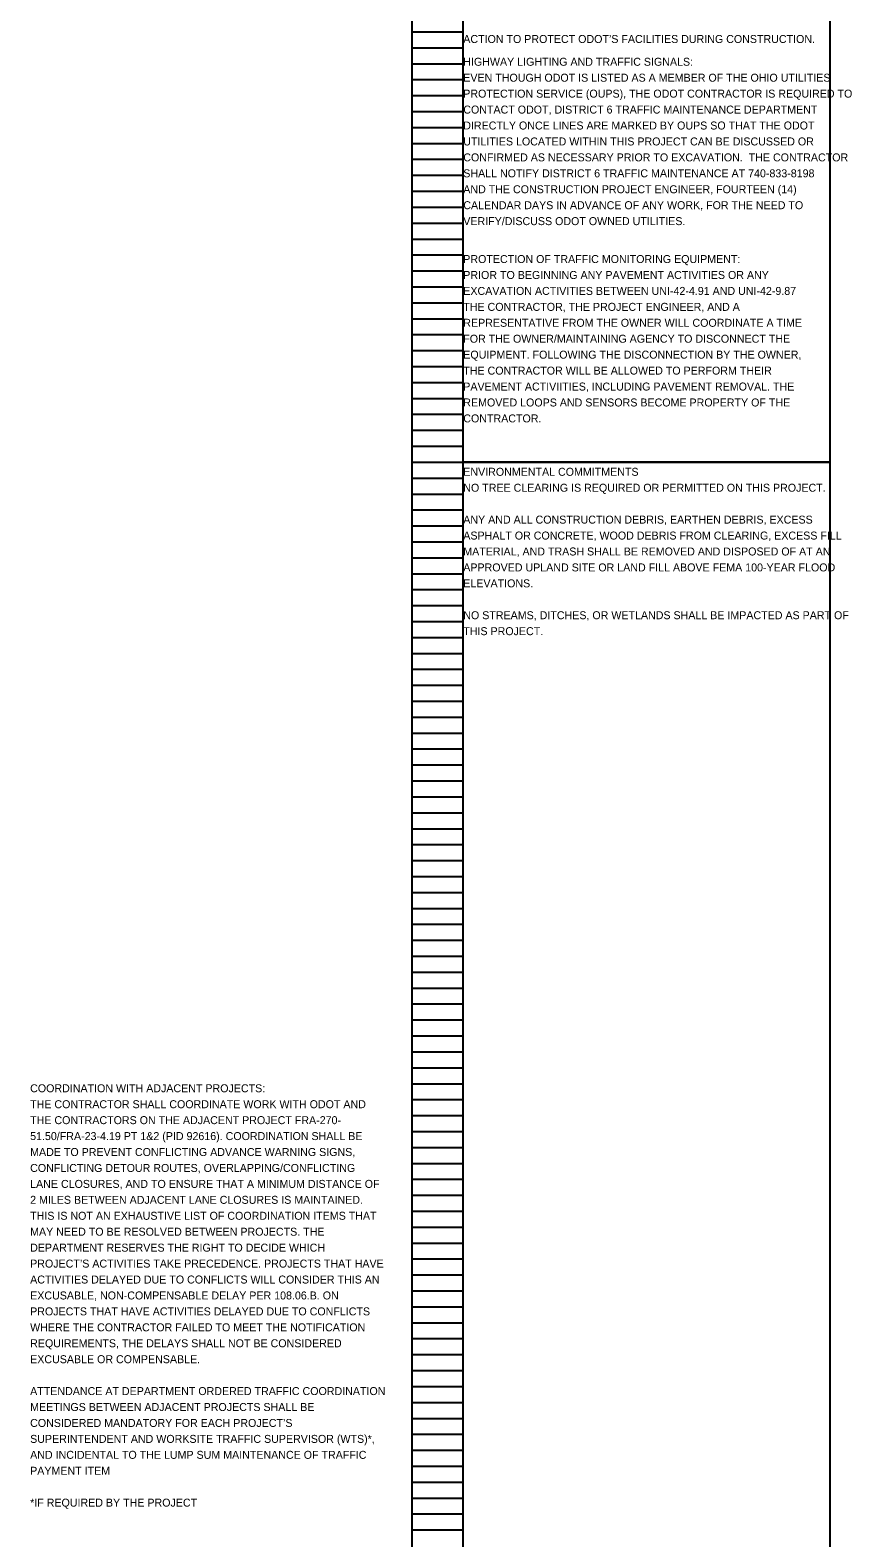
# Model space of a CAD drawing. Extents: x 16456 to 16500, y 5400 to 5823.
# Drawn here: x 16456.34 to 16470.77, y 5744.09 to 5770.58 of the extents above; entities that cross this region are included whole.
import ezdxf

# ---------------------------------------------------------------- set-up
doc = ezdxf.new("R2010")
doc.units = 0
for name, color, linetype in [('Default', 7, 'Continuous'), ('SC_Scratch1', 7, 'Continuous'), ('SH_Data', 7, 'Continuous')]:
    doc.layers.add(name, color=color, linetype=linetype)

msp = doc.modelspace()

# ---------------------------------------------------------------- linework, layer by layer
at = {"layer": 'SC_Scratch1'}
for points in [[(16463.949, 5783.152), (16470.389, 5783.152), (16470.389, 5762.992), (16463.949, 5762.992)], [(16463.949, 5762.992), (16470.389, 5762.992), (16470.389, 5742.832), (16463.949, 5742.832)]]:
    msp.add_lwpolyline(points, close=True, dxfattribs=at)
at = {"layer": 'SH_Data'}
for p, q in [((16463.049, 5762.992), (16463.049, 5783.152)), ((16463.949, 5762.992), (16463.949, 5783.152)), ((16463.049, 5770.552), (16463.949, 5770.552)), ((16463.049, 5770.272), (16463.949, 5770.272)), ((16463.049, 5769.992), (16463.949, 5769.992)), ((16463.049, 5769.712), (16463.949, 5769.712)), ((16463.049, 5769.432), (16463.949, 5769.432)), ((16463.049, 5769.152), (16463.949, 5769.152)), ((16463.049, 5768.872), (16463.949, 5768.872)), ((16463.049, 5768.592), (16463.949, 5768.592)), ((16463.049, 5768.312), (16463.949, 5768.312)), ((16463.049, 5768.032), (16463.949, 5768.032)), ((16463.049, 5767.752), (16463.949, 5767.752)), ((16463.049, 5767.472), (16463.949, 5767.472)), ((16463.049, 5767.192), (16463.949, 5767.192)), ((16463.049, 5766.912), (16463.949, 5766.912)), ((16463.049, 5766.632), (16463.949, 5766.632)), ((16463.049, 5766.352), (16463.949, 5766.352)), ((16463.049, 5766.072), (16463.949, 5766.072)), ((16463.049, 5765.792), (16463.949, 5765.792)), ((16463.049, 5765.512), (16463.949, 5765.512)), ((16463.049, 5765.232), (16463.949, 5765.232)), ((16463.049, 5764.952), (16463.949, 5764.952)), ((16463.049, 5764.672), (16463.949, 5764.672)), ((16463.049, 5764.392), (16463.949, 5764.392)), ((16463.049, 5764.112), (16463.949, 5764.112)), ((16463.049, 5763.832), (16463.949, 5763.832)), ((16463.049, 5763.552), (16463.949, 5763.552)), ((16463.049, 5763.272), (16463.949, 5763.272)), ((16463.049, 5742.832), (16463.049, 5762.992)), ((16463.049, 5762.992), (16463.949, 5762.992)), ((16463.049, 5762.992), (16463.949, 5762.992)), ((16463.949, 5742.832), (16463.949, 5762.992)), ((16463.049, 5762.712), (16463.949, 5762.712)), ((16463.049, 5762.432), (16463.949, 5762.432)), ((16463.049, 5762.152), (16463.949, 5762.152)), ((16463.049, 5761.872), (16463.949, 5761.872)), ((16463.049, 5761.592), (16463.949, 5761.592)), ((16463.049, 5761.312), (16463.949, 5761.312)), ((16463.049, 5761.032), (16463.949, 5761.032)), ((16463.049, 5760.752), (16463.949, 5760.752)), ((16463.049, 5760.472), (16463.949, 5760.472)), ((16463.049, 5760.192), (16463.949, 5760.192)), ((16463.049, 5759.912), (16463.949, 5759.912)), ((16463.049, 5759.632), (16463.949, 5759.632)), ((16463.049, 5759.352), (16463.949, 5759.352)), ((16463.049, 5759.072), (16463.949, 5759.072)), ((16463.049, 5758.792), (16463.949, 5758.792)), ((16463.049, 5758.512), (16463.949, 5758.512)), ((16463.049, 5758.232), (16463.949, 5758.232)), ((16463.049, 5757.952), (16463.949, 5757.952)), ((16463.049, 5757.672), (16463.949, 5757.672)), ((16463.049, 5757.392), (16463.949, 5757.392)), ((16463.049, 5757.112), (16463.949, 5757.112)), ((16463.049, 5756.832), (16463.949, 5756.832)), ((16463.049, 5756.552), (16463.949, 5756.552)), ((16463.049, 5756.272), (16463.949, 5756.272)), ((16463.049, 5755.992), (16463.949, 5755.992)), ((16463.049, 5755.712), (16463.949, 5755.712)), ((16463.049, 5755.432), (16463.949, 5755.432)), ((16463.049, 5755.152), (16463.949, 5755.152)), ((16463.049, 5754.872), (16463.949, 5754.872)), ((16463.049, 5754.592), (16463.949, 5754.592)), ((16463.049, 5754.312), (16463.949, 5754.312)), ((16463.049, 5754.032), (16463.949, 5754.032)), ((16463.049, 5753.752), (16463.949, 5753.752)), ((16463.049, 5753.472), (16463.949, 5753.472)), ((16463.049, 5753.192), (16463.949, 5753.192)), ((16463.049, 5752.912), (16463.949, 5752.912)), ((16463.049, 5752.632), (16463.949, 5752.632)), ((16463.049, 5752.352), (16463.949, 5752.352)), ((16463.049, 5752.072), (16463.949, 5752.072)), ((16463.049, 5751.792), (16463.949, 5751.792)), ((16463.049, 5751.512), (16463.949, 5751.512)), ((16463.049, 5751.232), (16463.949, 5751.232)), ((16463.049, 5750.952), (16463.949, 5750.952)), ((16463.049, 5750.672), (16463.949, 5750.672)), ((16463.049, 5750.392), (16463.949, 5750.392)), ((16463.049, 5750.112), (16463.949, 5750.112)), ((16463.049, 5749.832), (16463.949, 5749.832)), ((16463.049, 5749.552), (16463.949, 5749.552)), ((16463.049, 5749.272), (16463.949, 5749.272)), ((16463.049, 5748.992), (16463.949, 5748.992)), ((16463.049, 5748.712), (16463.949, 5748.712)), ((16463.049, 5748.432), (16463.949, 5748.432)), ((16463.049, 5748.152), (16463.949, 5748.152)), ((16463.049, 5747.872), (16463.949, 5747.872)), ((16463.049, 5747.592), (16463.949, 5747.592)), ((16463.049, 5747.312), (16463.949, 5747.312)), ((16463.049, 5747.032), (16463.949, 5747.032)), ((16463.049, 5746.752), (16463.949, 5746.752)), ((16463.049, 5746.472), (16463.949, 5746.472)), ((16463.049, 5746.192), (16463.949, 5746.192)), ((16463.049, 5745.912), (16463.949, 5745.912)), ((16463.049, 5745.632), (16463.949, 5745.632)), ((16463.049, 5745.352), (16463.949, 5745.352)), ((16463.049, 5745.072), (16463.949, 5745.072)), ((16463.049, 5744.792), (16463.949, 5744.792)), ((16463.049, 5744.512), (16463.949, 5744.512)), ((16463.049, 5744.232), (16463.949, 5744.232))]:
    msp.add_line(p, q, dxfattribs=at)

# ---------------------------------------------------------------- texts
at = {"layer": 'Default'}
for s, p in [('ACTION TO PROTECT ODOT’S FACILITIES DURING CONSTRUCTION.', (16463.949, 5770.356)), ('HIGHWAY LIGHTING AND TRAFFIC SIGNALS:', (16463.949, 5769.956)), ('EVEN THOUGH ODOT IS LISTED AS A MEMBER OF THE OHIO UTILITIES ', (16463.949, 5769.676)), ('PROTECTION SERVICE (OUPS), THE ODOT CONTRACTOR IS REQUIRED TO ', (16463.949, 5769.396)), ('CONTACT ODOT, DISTRICT 6 TRAFFIC MAINTENANCE DEPARTMENT ', (16463.949, 5769.116)), ('DIRECTLY ONCE LINES ARE MARKED BY OUPS SO THAT THE ODOT ', (16463.949, 5768.836)), ('UTILITIES LOCATED WITHIN THIS PROJECT CAN BE DISCUSSED OR ', (16463.949, 5768.556)), ('CONFIRMED AS NECESSARY PRIOR TO EXCAVATION.  THE CONTRACTOR ', (16463.949, 5768.276)), ('SHALL NOTIFY DISTRICT 6 TRAFFIC MAINTENANCE AT 740-833-8198 ', (16463.949, 5767.996)), ('AND THE CONSTRUCTION PROJECT ENGINEER, FOURTEEN (14) ', (16463.949, 5767.716)), ('CALENDAR DAYS IN ADVANCE OF ANY WORK, FOR THE NEED TO ', (16463.949, 5767.436)), ('VERIFY/DISCUSS ODOT OWNED UTILITIES.', (16463.949, 5767.156)), ('PROTECTION OF TRAFFIC MONITORING EQUIPMENT:', (16463.949, 5766.49)), ('PRIOR TO BEGINNING ANY PAVEMENT ACTIVITIES OR ANY ', (16463.949, 5766.21)), ('EXCAVATION ACTIVITIES BETWEEN UNI-42-4.91 AND UNI-42-9.87 ', (16463.949, 5765.93)), ('THE CONTRACTOR, THE PROJECT ENGINEER, AND A ', (16463.949, 5765.65)), ('REPRESENTATIVE FROM THE OWNER WILL COORDINATE A TIME ', (16463.949, 5765.37)), ('FOR THE OWNER/MAINTAINING AGENCY TO DISCONNECT THE ', (16463.949, 5765.09)), ('EQUIPMENT. FOLLOWING THE DISCONNECTION BY THE OWNER, ', (16463.949, 5764.81)), ('THE CONTRACTOR WILL BE ALLOWED TO PERFORM THEIR ', (16463.949, 5764.53)), ('PAVEMENT ACTIVIITIES, INCLUDING PAVEMENT REMOVAL. THE ', (16463.949, 5764.25)), ('REMOVED LOOPS AND SENSORS BECOME PROPERTY OF THE ', (16463.949, 5763.97)), ('CONTRACTOR.', (16463.949, 5763.69)), ('ENVIRONMENTAL COMMITMENTS', (16463.949, 5762.752)), ('NO TREE CLEARING IS REQUIRED OR PERMITTED ON THIS PROJECT.', (16463.949, 5762.472)), ('ANY AND ALL CONSTRUCTION DEBRIS, EARTHEN DEBRIS, EXCESS ', (16463.949, 5761.912)), ('ASPHALT OR CONCRETE, WOOD DEBRIS FROM CLEARING, EXCESS FILL ', (16463.949, 5761.632)), ('MATERIAL, AND TRASH SHALL BE REMOVED AND DISPOSED OF AT AN ', (16463.949, 5761.352)), ('APPROVED UPLAND SITE OR LAND FILL ABOVE FEMA 100-YEAR FLOOD ', (16463.949, 5761.072)), ('ELEVATIONS.', (16463.949, 5760.792)), ('NO STREAMS, DITCHES, OR WETLANDS SHALL BE IMPACTED AS PART OF ', (16463.949, 5760.232)), ('THIS PROJECT.', (16463.949, 5759.952)), ('COORDINATION WITH ADJACENT PROJECTS:', (16456.341, 5751.921)), ('THE CONTRACTOR SHALL COORDINATE WORK WITH ODOT AND ', (16456.341, 5751.641)), ('THE CONTRACTORS ON THE ADJACENT PROJECT FRA-270-', (16456.341, 5751.361)), ('51.50/FRA-23-4.19 PT 1&2 (PID 92616). COORDINATION SHALL BE ', (16456.341, 5751.081)), ('MADE TO PREVENT CONFLICTING ADVANCE WARNING SIGNS, ', (16456.341, 5750.801)), ('CONFLICTING DETOUR ROUTES, OVERLAPPING/CONFLICTING ', (16456.341, 5750.521)), ('LANE CLOSURES, AND TO ENSURE THAT A MINIMUM DISTANCE OF ', (16456.341, 5750.241)), ('2 MILES BETWEEN ADJACENT LANE CLOSURES IS MAINTAINED. ', (16456.341, 5749.961)), ('THIS IS NOT AN EXHAUSTIVE LIST OF COORDINATION ITEMS THAT ', (16456.341, 5749.681)), ('MAY NEED TO BE RESOLVED BETWEEN PROJECTS. THE ', (16456.341, 5749.401)), ('DEPARTMENT RESERVES THE RIGHT TO DECIDE WHICH ', (16456.341, 5749.121)), ('PROJECT’S ACTIVITIES TAKE PRECEDENCE. PROJECTS THAT HAVE ', (16456.341, 5748.841)), ('ACTIVITIES DELAYED DUE TO CONFLICTS WILL CONSIDER THIS AN ', (16456.341, 5748.561)), ('EXCUSABLE, NON-COMPENSABLE DELAY PER 108.06.B. ON ', (16456.341, 5748.281)), ('PROJECTS THAT HAVE ACTIVITIES DELAYED DUE TO CONFLICTS ', (16456.341, 5748.001)), ('WHERE THE CONTRACTOR FAILED TO MEET THE NOTIFICATION ', (16456.341, 5747.721)), ('REQUIREMENTS, THE DELAYS SHALL NOT BE CONSIDERED ', (16456.341, 5747.441)), ('EXCUSABLE OR COMPENSABLE.', (16456.341, 5747.161)), ('ATTENDANCE AT DEPARTMENT ORDERED TRAFFIC COORDINATION ', (16456.341, 5746.601)), ('MEETINGS BETWEEN ADJACENT PROJECTS SHALL BE ', (16456.341, 5746.321)), ('CONSIDERED MANDATORY FOR EACH PROJECT’S ', (16456.341, 5746.041)), ('SUPERINTENDENT AND WORKSITE TRAFFIC SUPERVISOR (WTS)*, ', (16456.341, 5745.761)), ('AND INCIDENTAL TO THE LUMP SUM MAINTENANCE OF TRAFFIC ', (16456.341, 5745.481)), ('PAYMENT ITEM', (16456.341, 5745.201)), ('*IF REQUIRED BY THE PROJECT', (16456.341, 5744.641))]:
    msp.add_text(s, height=0.14, dxfattribs=at).set_placement(p)

doc.saveas('drawing.dxf')
